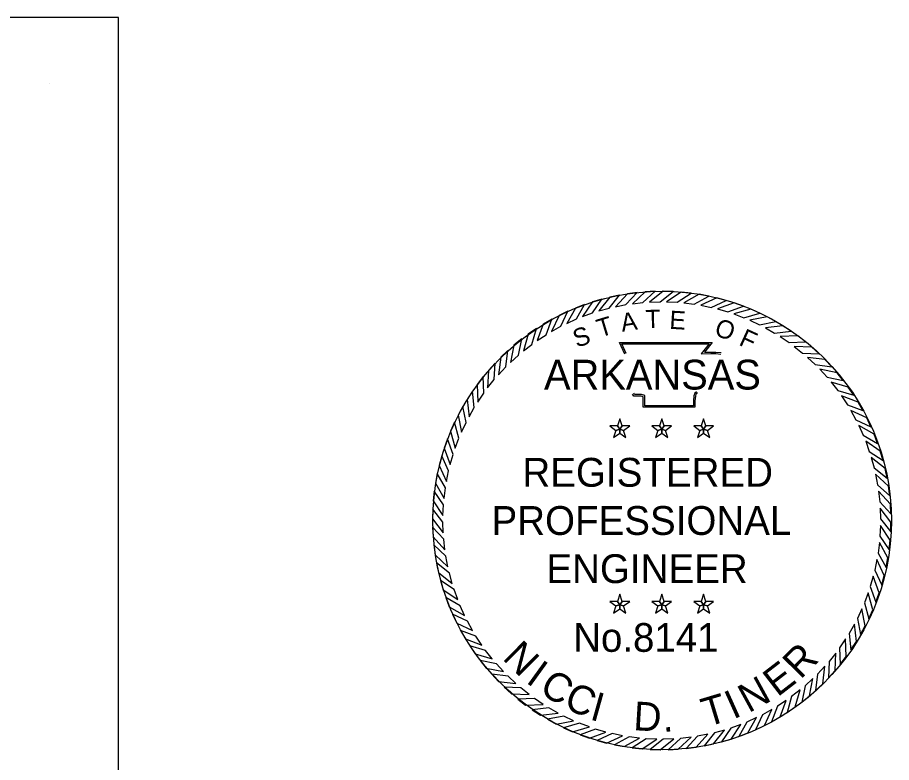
# Model space of a CAD drawing. Extents: x 0 to 19, y -0.6 to 11.3.
# Drawn here: x 16.736 to 19.023, y 9.05 to 11 of the extents above; entities that cross this region are included whole.
import ezdxf

# ---------------------------------------------------------------- set-up
doc = ezdxf.new("R2010")
doc.units = 0
for name, color, linetype in [('G-ANNO-STMP', 7, 'Continuous'), ('G-ANNO-TEXT', 7, 'Continuous'), ('G-Border-Paper', 7, 'Continuous'), ('G-No Plot-Stamp-2', 7, 'Continuous')]:
    doc.layers.add(name, color=color, linetype=linetype)

msp = doc.modelspace()

# ---------------------------------------------------------------- linework, layer by layer
at = {"layer": 'G-ANNO-STMP'}
for points in [[(18.3112, 10.2732), (18.2859, 10.2679), (18.2573, 10.2319), (18.2842, 10.2393)], [(18.3578, 10.2801), (18.3322, 10.2768), (18.3008, 10.2431), (18.3282, 10.2484)], [(18.4048, 10.2833), (18.379, 10.282), (18.3451, 10.2509), (18.3728, 10.254)], [(18.4519, 10.2828), (18.4261, 10.2835), (18.3899, 10.2552), (18.4177, 10.2561)], [(18.4988, 10.2786), (18.4732, 10.2813), (18.4348, 10.256), (18.4627, 10.2546)], [(18.5453, 10.2707), (18.5199, 10.2755), (18.4797, 10.2532), (18.5073, 10.2497)], [(18.2203, 10.2486), (18.1962, 10.2394), (18.1735, 10.1994), (18.1989, 10.2109)], [(18.2652, 10.2627), (18.2405, 10.2554), (18.2148, 10.2173), (18.241, 10.2268)], [(18.591, 10.2592), (18.5661, 10.266), (18.5242, 10.2469), (18.5515, 10.2412)], [(18.6356, 10.2442), (18.6113, 10.2529), (18.5681, 10.2371), (18.5949, 10.2294)], [(18.1766, 10.2311), (18.1533, 10.22), (18.1338, 10.1783), (18.1582, 10.1918)], [(18.6789, 10.2257), (18.6554, 10.2362), (18.6111, 10.224), (18.6372, 10.2141)], [(18.1344, 10.2101), (18.112, 10.1973), (18.0959, 10.1542), (18.1192, 10.1695)], [(18.7207, 10.2039), (18.698, 10.2162), (18.6529, 10.2074), (18.6781, 10.1956)], [(18.0939, 10.1859), (18.0726, 10.1714), (18.06, 10.1272), (18.082, 10.1443)], [(18.7606, 10.1788), (18.739, 10.1929), (18.6933, 10.1877), (18.7175, 10.1739)], [(18.0555, 10.1587), (18.0354, 10.1425), (18.0263, 10.0974), (18.0469, 10.1162)], [(18.7984, 10.1507), (18.778, 10.1665), (18.732, 10.1649), (18.7551, 10.1492)], [(18.8339, 10.1197), (18.8148, 10.137), (18.7688, 10.1391), (18.7906, 10.1216)], [(18.0194, 10.1284), (18.0006, 10.1107), (17.995, 10.0651), (18.0141, 10.0854)], [(18.8669, 10.0861), (18.8491, 10.1048), (18.8035, 10.1104), (18.8238, 10.0914)], [(17.9857, 10.0955), (17.9684, 10.0764), (17.9664, 10.0304), (17.9838, 10.0522)], [(18.8971, 10.0499), (18.8809, 10.07), (18.8358, 10.0792), (18.8546, 10.0586)], [(17.9547, 10.06), (17.939, 10.0396), (17.9406, 9.9936), (17.9562, 10.0167)], [(18.9244, 10.0115), (18.9098, 10.0328), (18.8656, 10.0455), (18.8827, 10.0235)], [(17.9266, 10.0222), (17.9125, 10.0006), (17.9177, 9.9549), (17.9315, 9.9791)], [(18.9485, 9.9711), (18.9357, 9.9935), (18.8926, 10.0096), (18.9079, 9.9863)], [(17.9016, 9.9823), (17.8892, 9.9596), (17.898, 9.9145), (17.9099, 9.9397)], [(18.3122, 9.9224), (18.3184, 9.9309), (18.3122, 9.9499), (18.3061, 9.9309)], [(18.4219, 9.9224), (18.4281, 9.9309), (18.4219, 9.9499), (18.4158, 9.9309)], [(18.5317, 9.9224), (18.5378, 9.9309), (18.5317, 9.9499), (18.5255, 9.9309)], [(18.9695, 9.9289), (18.9584, 9.9522), (18.9167, 9.9716), (18.9302, 9.9472)], [(17.8798, 9.9405), (17.8692, 9.917), (17.8815, 9.8727), (17.8913, 9.8987)], [(18.3122, 9.9224), (18.3061, 9.9309), (18.2861, 9.9309), (18.3023, 9.9192)], [(18.3122, 9.9224), (18.3222, 9.9192), (18.3383, 9.9309), (18.3184, 9.9309)], [(18.4219, 9.9224), (18.4158, 9.9309), (18.3958, 9.9309), (18.412, 9.9192)], [(18.4219, 9.9224), (18.4319, 9.9192), (18.448, 9.9309), (18.4281, 9.9309)], [(18.5317, 9.9224), (18.5255, 9.9309), (18.5056, 9.9309), (18.5217, 9.9192)], [(18.5317, 9.9224), (18.5416, 9.9192), (18.5577, 9.9309), (18.5378, 9.9309)], [(18.987, 9.8852), (18.9779, 9.9093), (18.9378, 9.9319), (18.9493, 9.9065)], [(18.3122, 9.9224), (18.3023, 9.9192), (18.2961, 9.9003), (18.3122, 9.912)], [(18.3122, 9.9224), (18.3122, 9.912), (18.3283, 9.9003), (18.3222, 9.9192)], [(18.4219, 9.9224), (18.412, 9.9192), (18.4058, 9.9003), (18.4219, 9.912)], [(18.4219, 9.9224), (18.4219, 9.912), (18.4381, 9.9003), (18.4319, 9.9192)], [(18.5317, 9.9224), (18.5217, 9.9192), (18.5155, 9.9003), (18.5317, 9.912)], [(18.5317, 9.9224), (18.5317, 9.912), (18.5478, 9.9003), (18.5416, 9.9192)], [(17.8613, 9.8972), (17.8526, 9.8729), (17.8683, 9.8297), (17.8761, 9.8564)], [(19.0011, 9.8402), (18.9939, 9.865), (18.9557, 9.8907), (18.9652, 9.8645)], [(17.8462, 9.8525), (17.8395, 9.8276), (17.8586, 9.7858), (17.8642, 9.8131)], [(19.0116, 9.7943), (19.0063, 9.8195), (18.9703, 9.8482), (18.9777, 9.8213)], [(17.8347, 9.8069), (17.83, 9.7815), (17.8523, 9.7413), (17.8558, 9.7689)], [(19.0185, 9.7477), (19.0152, 9.7733), (18.9816, 9.8046), (18.9868, 9.7772)], [(17.8269, 9.7604), (17.8241, 9.7347), (17.8495, 9.6964), (17.8508, 9.7242)], [(19.0217, 9.7007), (19.0204, 9.7264), (18.9893, 9.7603), (18.9924, 9.7326)], [(17.8227, 9.7135), (17.8219, 9.6877), (17.8503, 9.6514), (17.8494, 9.6793)], [(19.0212, 9.6536), (19.0219, 9.6793), (18.9936, 9.7156), (18.9945, 9.6877)], [(17.8222, 9.6664), (17.8235, 9.6406), (17.8545, 9.6067), (17.8515, 9.6344)], [(19.017, 9.6066), (19.0198, 9.6323), (18.9944, 9.6706), (18.9931, 9.6428)], [(17.8254, 9.6194), (17.8287, 9.5938), (17.8623, 9.5624), (17.8571, 9.5898)], [(19.0091, 9.5602), (19.0139, 9.5855), (18.9916, 9.6258), (18.9881, 9.5981)], [(17.8322, 9.5728), (17.8375, 9.5475), (17.8735, 9.5189), (17.8662, 9.5458)], [(18.9976, 9.5145), (19.0044, 9.5394), (18.9853, 9.5812), (18.9797, 9.5539)], [(17.8427, 9.5268), (17.85, 9.5021), (17.8881, 9.4764), (17.8787, 9.5026)], [(18.9826, 9.4698), (18.9913, 9.4941), (18.9755, 9.5374), (18.9678, 9.5106)], [(18.9641, 9.4265), (18.9747, 9.4501), (18.9624, 9.4944), (18.9525, 9.4683)], [(17.8568, 9.4819), (17.866, 9.4578), (17.906, 9.4351), (17.8946, 9.4605)], [(18.3122, 9.463), (18.3061, 9.4715), (18.2861, 9.4715), (18.3023, 9.4598)], [(18.3122, 9.463), (18.3184, 9.4715), (18.3122, 9.4904), (18.3061, 9.4715)], [(18.3122, 9.463), (18.3222, 9.4598), (18.3383, 9.4715), (18.3184, 9.4715)], [(18.4219, 9.463), (18.4158, 9.4715), (18.3958, 9.4715), (18.412, 9.4598)], [(18.4219, 9.463), (18.4281, 9.4715), (18.4219, 9.4904), (18.4158, 9.4715)], [(18.4219, 9.463), (18.4319, 9.4598), (18.448, 9.4715), (18.4281, 9.4715)], [(18.5317, 9.463), (18.5255, 9.4715), (18.5056, 9.4715), (18.5217, 9.4598)], [(18.5317, 9.463), (18.5378, 9.4715), (18.5317, 9.4904), (18.5255, 9.4715)], [(18.5317, 9.463), (18.5416, 9.4598), (18.5577, 9.4715), (18.5378, 9.4715)], [(18.3122, 9.463), (18.3023, 9.4598), (18.2961, 9.4408), (18.3122, 9.4525)], [(18.3122, 9.463), (18.3122, 9.4525), (18.3283, 9.4408), (18.3222, 9.4598)], [(18.4219, 9.463), (18.412, 9.4598), (18.4058, 9.4408), (18.4219, 9.4525)], [(18.4219, 9.463), (18.4219, 9.4525), (18.4381, 9.4408), (18.4319, 9.4598)], [(18.5317, 9.463), (18.5217, 9.4598), (18.5155, 9.4408), (18.5317, 9.4525)], [(18.5317, 9.463), (18.5317, 9.4525), (18.5478, 9.4408), (18.5416, 9.4598)], [(18.9423, 9.3848), (18.9546, 9.4074), (18.9459, 9.4526), (18.934, 9.4273)], [(17.8744, 9.4382), (17.8854, 9.4148), (17.9271, 9.3954), (17.9137, 9.4198)], [(18.9172, 9.3449), (18.9313, 9.3665), (18.9261, 9.4122), (18.9123, 9.3879)], [(17.8953, 9.3959), (17.9082, 9.3736), (17.9513, 9.3575), (17.9359, 9.3808)], [(17.9195, 9.3555), (17.9341, 9.3342), (17.9783, 9.3215), (17.9612, 9.3436)], [(18.8891, 9.307), (18.9049, 9.3275), (18.9033, 9.3734), (18.8876, 9.3504)], [(18.8582, 9.2715), (18.8755, 9.2907), (18.8775, 9.3366), (18.8601, 9.3149)], [(17.9468, 9.3171), (17.963, 9.297), (18.0081, 9.2879), (17.9893, 9.3085)], [(18.8245, 9.2386), (18.8432, 9.2563), (18.8489, 9.302), (18.8298, 9.2816)], [(17.977, 9.281), (17.9947, 9.2622), (18.0404, 9.2566), (18.02, 9.2757)], [(18.7883, 9.2084), (18.8084, 9.2246), (18.8176, 9.2696), (18.797, 9.2509)], [(18.01, 9.2473), (18.0291, 9.23), (18.075, 9.228), (18.0533, 9.2454)], [(18.0455, 9.2163), (18.0659, 9.2006), (18.1119, 9.2022), (18.0888, 9.2178)], [(18.7499, 9.1811), (18.7712, 9.1957), (18.7839, 9.2399), (18.7619, 9.2228)], [(18.7095, 9.1569), (18.7319, 9.1698), (18.748, 9.2128), (18.7247, 9.1975)], [(18.0833, 9.1882), (18.1049, 9.1741), (18.1506, 9.1793), (18.1264, 9.1931)], [(18.6673, 9.136), (18.6906, 9.147), (18.71, 9.1887), (18.6856, 9.1753)], [(18.1232, 9.1632), (18.1458, 9.1508), (18.191, 9.1596), (18.1657, 9.1714)], [(18.1649, 9.1413), (18.1885, 9.1308), (18.2328, 9.1431), (18.2067, 9.1529)], [(18.5786, 9.1043), (18.6034, 9.1116), (18.6291, 9.1497), (18.6029, 9.1403)], [(18.6236, 9.1184), (18.6477, 9.1276), (18.6703, 9.1676), (18.6449, 9.1561)], [(18.2083, 9.1228), (18.2326, 9.1142), (18.2758, 9.1299), (18.249, 9.1377)], [(18.5327, 9.0938), (18.5579, 9.0991), (18.5866, 9.1351), (18.5597, 9.1278)], [(18.2529, 9.1078), (18.2778, 9.1011), (18.3197, 9.1201), (18.2924, 9.1258)], [(18.2986, 9.0963), (18.324, 9.0916), (18.3642, 9.1139), (18.3365, 9.1173)], [(18.345, 9.0885), (18.3707, 9.0857), (18.4091, 9.1111), (18.3812, 9.1124)], [(18.392, 9.0843), (18.4178, 9.0835), (18.454, 9.1118), (18.4261, 9.1109)], [(18.4391, 9.0837), (18.4649, 9.085), (18.4988, 9.1161), (18.4711, 9.113)], [(18.4861, 9.0869), (18.5117, 9.0903), (18.543, 9.1239), (18.5157, 9.1187)]]:
    msp.add_lwpolyline(points, close=True, dxfattribs=at)
for points in [[(18.3258, 10.119), (18.3118, 10.1493), (18.5538, 10.1494), (18.5336, 10.124), (18.5501, 10.1242), (18.5638, 10.1244), (18.5775, 10.1229)], [(18.3293, 10.1206), (18.3178, 10.1455), (18.5459, 10.1456), (18.5256, 10.1201), (18.5501, 10.1204), (18.5636, 10.1206), (18.5771, 10.1191)], [(18.5133, 10.0205), (18.5082, 10.0164), (18.5064, 10.0099), (18.505, 9.9969), (18.505, 9.9838), (18.3776, 9.9838), (18.3776, 10.0025), (18.3776, 10.0104), (18.3688, 10.013), (18.3511, 10.013), (18.3488, 10.0165)], [(18.5157, 10.0176), (18.5116, 10.0142), (18.5102, 10.0092), (18.5088, 9.9966), (18.5088, 9.9799), (18.3737, 9.9799), (18.3737, 10.0025), (18.3737, 10.0075), (18.3683, 10.0092), (18.349, 10.0092), (18.3456, 10.0144)]]:
    msp.add_lwpolyline(points, dxfattribs=at)
at = {"layer": 'G-ANNO-TEXT'}
msp.add_line((16.821, 10.8269), (16.821, 10.8269), dxfattribs=at)
at = {"layer": 'G-Border-Paper'}
msp.add_lwpolyline([(17, 11), (0, 11), (0, 0), (17, 0)], close=True, dxfattribs=at)
at = {"layer": 'G-No Plot-Stamp-2'}
msp.add_circle((18.4233, 9.6835), 0.6, dxfattribs=at)

# ---------------------------------------------------------------- texts
at = {"layer": 'G-ANNO-STMP'}
for s, height, rotation, p in [('A', 0.0477, 8.6788, (18.3184, 10.1773)), ('T', 0.0477, 1.4789, (18.3801, 10.1868)), ('E', 0.0477, 356.672, (18.4412, 10.1853)), ('T', 0.0477, 16.9015, (18.2605, 10.1621)), ('O', 0.0477, 341.2218, (18.5571, 10.1689)), ('S', 0.0477, 19.7726, (18.1998, 10.1349)), ('F', 0.0477, 335.3628, (18.6214, 10.1438)), ('N', 0.0754, 315.2676, (18.0028, 9.3216)), ('R', 0.0754, 45.478, (18.7853, 9.2657)), ('I', 0.0754, 324.2141, (18.0641, 9.2609)), ('E', 0.0754, 37.6498, (18.725, 9.2201)), ('C', 0.0754, 328.6873, (18.0982, 9.2342)), ('N', 0.0754, 28.7033, (18.6493, 9.1786)), ('C', 0.0754, 336.5155, (18.1624, 9.1943)), ('I', 0.0754, 344.3437, (18.2314, 9.1635)), ('T', 0.0754, 16.7747, (18.54, 9.1425)), ('I', 0.0754, 24.2301, (18.6092, 9.1624)), ('D', 0.0754, 356.6451, (18.3466, 9.1349)), ('.', 0.0754, 4.846, (18.4256, 9.1298))]:
    msp.add_text(s, height=height, rotation=rotation, dxfattribs=at).set_placement(p)
for s, height, p in [('ARKANSAS', 0.07791, (18.114, 10.0263)), ('REGISTERED', 0.07543, (18.0574, 9.7719)), ('PROFESSIONAL', 0.07543, (17.9765, 9.6458)), ('ENGINEER', 0.07543, (18.1202, 9.5197)), ('No.8141', 0.07513, (18.1905, 9.3398))]:
    msp.add_text(s, height=height, dxfattribs=at).set_placement(p)

doc.saveas('drawing.dxf')
